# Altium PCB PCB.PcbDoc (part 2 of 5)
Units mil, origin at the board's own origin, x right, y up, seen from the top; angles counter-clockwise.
Board outline 8070.87 x 4448.94 mil, 4 copper layers (Top Layer, Layer 1, Layer 2, Bottom Layer), stack 23.756 mil thick; 263 components, 330 nets, 1677 pads, 1186 vias.
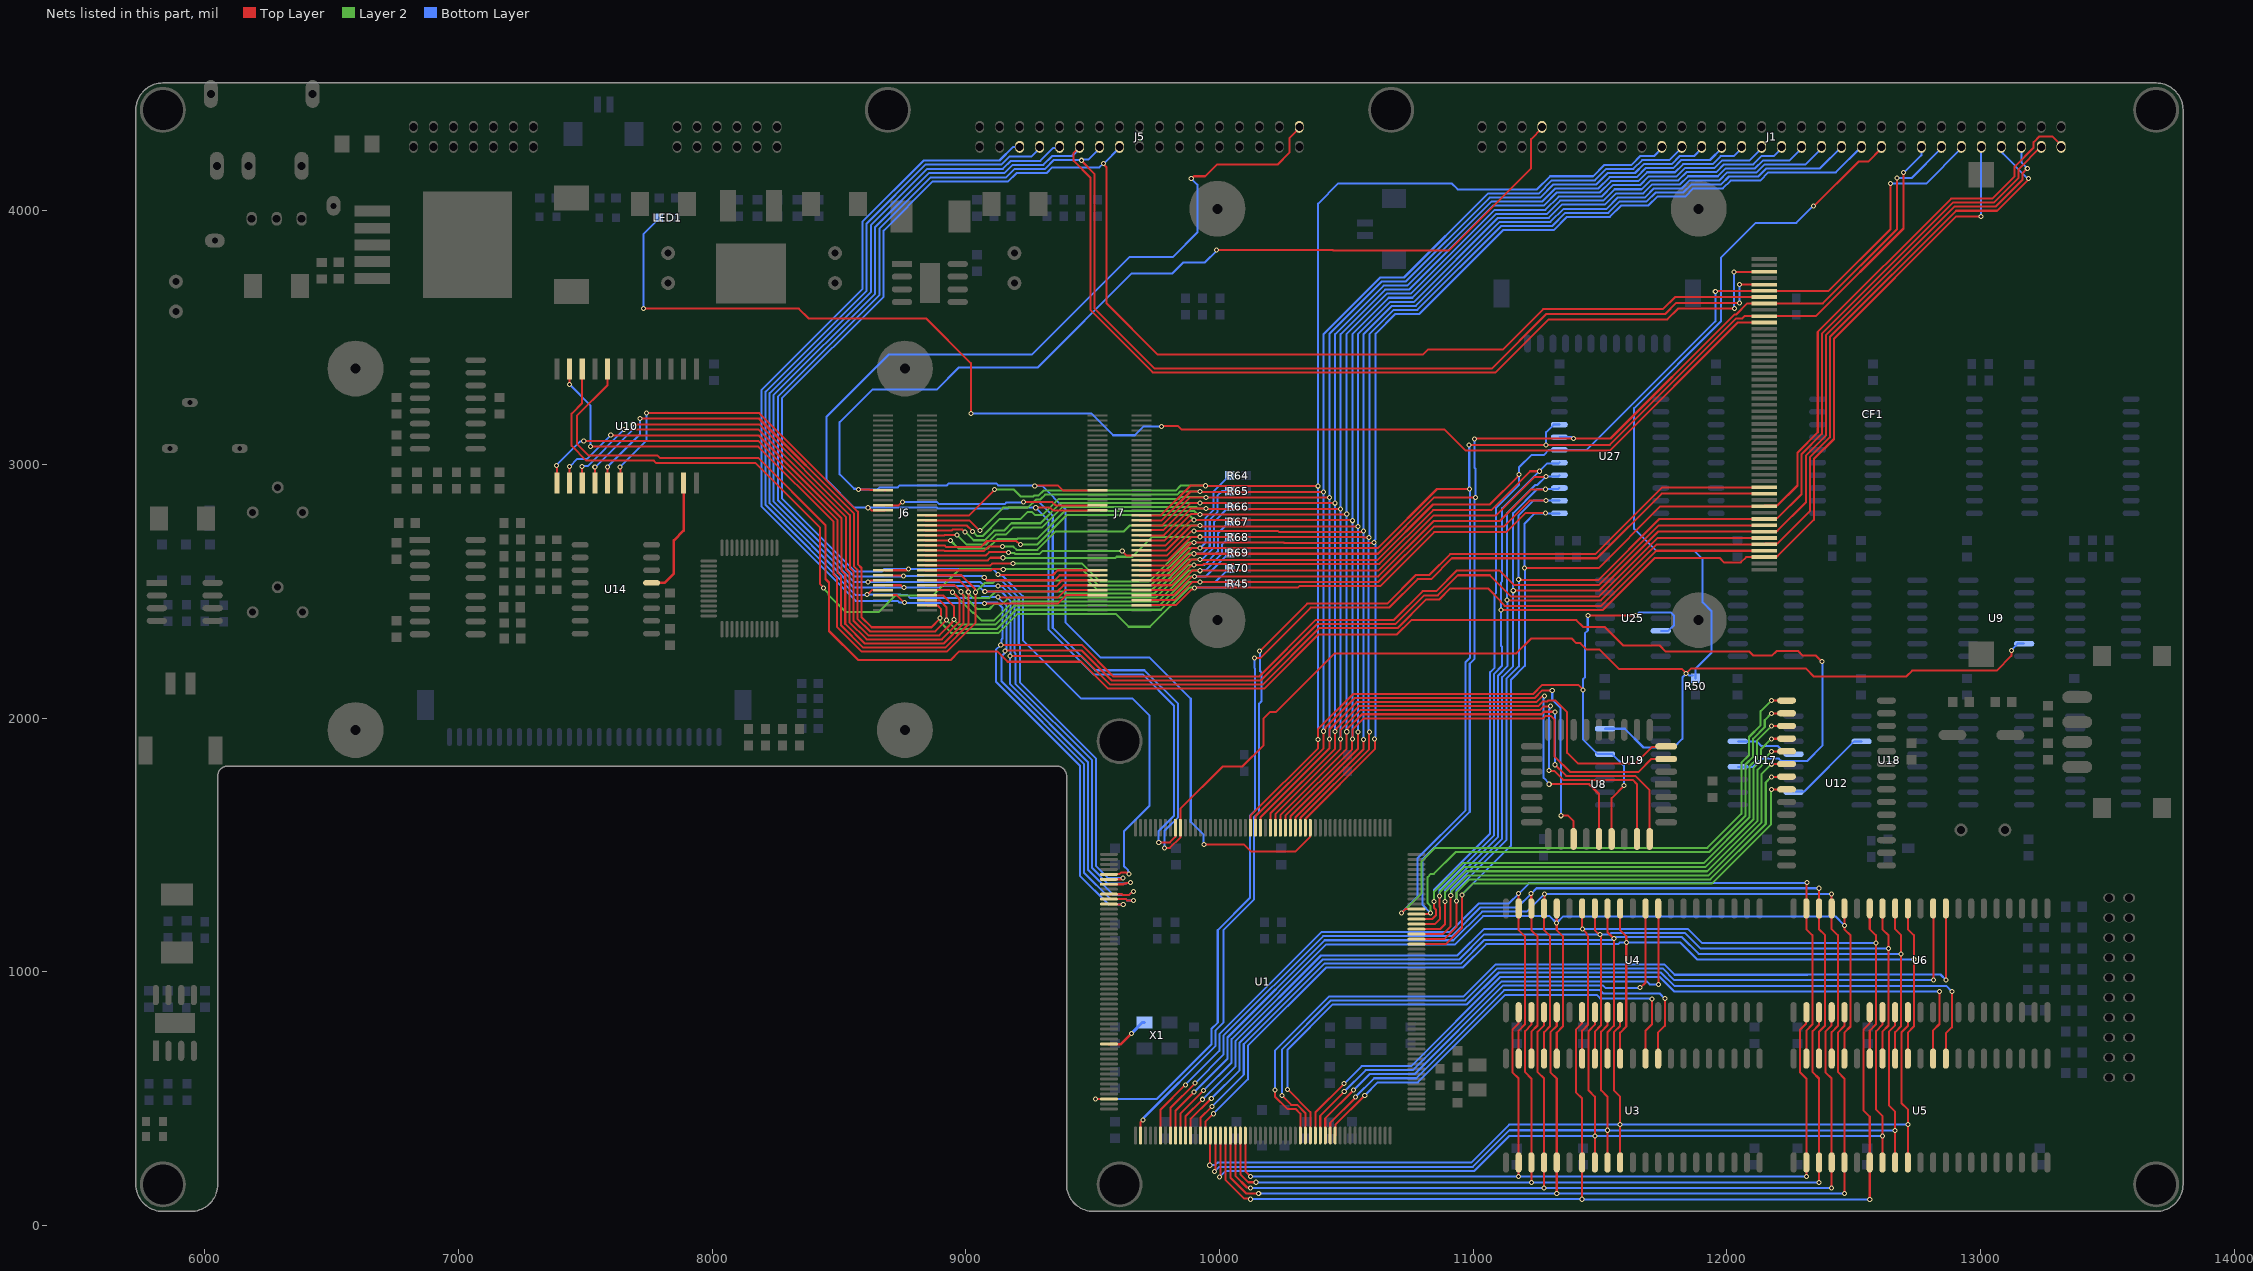
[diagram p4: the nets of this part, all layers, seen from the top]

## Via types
v1: diameter 20, hole 12, Top Layer to Bottom Layer, tented both sides, 1165 vias
v2: diameter 19.68, hole 11.81, Top Layer to Bottom Layer, tented both sides, 10 vias
v3: diameter 27.56, hole 27.56, Top Layer to Bottom Layer, 4 vias
v4: diameter 35.43, hole 35.43, Top Layer to Bottom Layer, 2 vias
v5: diameter 55.12, hole 55.12, Top Layer to Bottom Layer, 2 vias
v6: diameter 66.93, hole 66.93, Top Layer to Bottom Layer, 2 vias
v7: diameter 78.74, hole 78.74, Top Layer to Bottom Layer, 1 vias

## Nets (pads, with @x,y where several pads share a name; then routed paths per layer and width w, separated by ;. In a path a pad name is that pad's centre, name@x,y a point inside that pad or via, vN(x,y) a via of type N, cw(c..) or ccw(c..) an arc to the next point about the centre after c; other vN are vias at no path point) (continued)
A9: J1.19 J6.39 J7.39 U1.185 U8.26 U19.13 U25.5 | length 8598.6
  Top Layer w8: J6.39@8838.58,2799.21 9013.31,2799.21 9113,2898.9 v1(9113,2901) ; J7.39@9685.04,2799.21 9769.49,2799.21 9886.2,2915.92 v1(9946,2915.92) ; v1@9946.54,2916.46 9949,2914 v1(10389,2914) ; U1.185@10122.05,1567.56 10122.05,1614.3 10389,1881.25 v1(10389,1916) 10389,1957.11 10526.89,2095 11236.61,2095 11272.61,2131 11414,2131 v1(11434,2111) ; v1(11453,2404.13) v1@11640,2404.13 ; U8.26@11546.46,1523.62 11546.46,1684.56 v1(11595.89,1734)
  Layer 2 w8: v1(9113,2901) 9189,2901 9216.53,2873.47 9266.53,2873.47 9270.73,2877.66 9287.74,2877.66 9306.52,2896.44 9827.21,2896.44 9846.69,2915.92 v1(9946,2915.92)
  Bottom Layer w8: v1(10389,1916) v1(10389,2914) 10389,4027.75 10469.22,4107.97 10915.18,4107.97 10939.15,4084 11252.2,4084 11304.2,4136 11473.25,4136 11518.25,4181 11625,4181 11660,4216 11714.03,4216 11744.09,4246.06 J1.19@11744.09,4251.97 ; v1(11453,2404.13) 11452.16,2403.29 11452.16,2344.79 11441,2333.63 11441,2160.82 11434,2153.82 v1(11434,2111) 11434,1914.96 11491.16,1857.8 11549.16,1857.8 11595.94,1811.02 11595.94,1734.06 v1(11595.89,1734) ; v1(11640,2405) 11643.25,2405 11654.95,2416.7 11778.68,2416.7 11792.16,2403.23 11792.16,2366.7 11769.16,2343.7 U25.5@11740.16,2343.7
A10: J1.21 J6.37 J7.37 U1.184 U8.23 | length 7325.6
  Top Layer w8: J6.37@8838.58,2779.53 9014.43,2779.53 9054.95,2739 v1(9055.84,2739) ; J7.37@9685.04,2779.53 9772.43,2779.53 9885.94,2893.04 v1(9923.5,2893.04) 9924.54,2892 v1(10411,2892) ; U1.184@10141.73,1567.56 10142.46,1568.29 10142.46,1612.09 10411,1880.63 10411,1951.25 10418,1958.25 10418,1962.74 10534.26,2079 11243.24,2079 11273.24,2109 v1(11312.26,2109) ; v1(11347,1615) 11375,1615 11396.46,1593.54 U8.23@11396.46,1523.62
  Layer 2 w8: v1(9055.84,2739) 9056.73,2739 9147.06,2829.33 9245.02,2829.33 9277.35,2861.66 9294.37,2861.66 9313.15,2880.44 9833.83,2880.44 9846.43,2893.04 v1(9923.5,2893.04)
  Bottom Layer w8: v1(10411,1948) v1(10411,2892) 10411,3514 10634,3737 10727.73,3737 11058.57,4067.85 11258.67,4067.85 11310.67,4119.85 11479.95,4119.85 11524.95,4164.85 11631.69,4164.85 11666.69,4199.85 11773.85,4199.85 11822.83,4248.83 J1.21@11822.83,4251.97 ; v1(11312.26,2109) 11312.26,2072.74 11344.32,2040.68 11344.32,1932.94 11344,1932.62 11344,1824.89 11347,1821.89 v1(11347,1615)
A11: J1.23 J6.35 J7.35 U1.183 U8.25 | length 7522.2
  Top Layer w8: J6.35@8838.58,2759.84 9003,2759.84 v1(9026.84,2736.01) ; J7.35@9685.04,2759.84 9775.37,2759.84 9885.6,2870.07 9947.57,2870.07 v1(9947.65,2870) v1(10434,2870) ; U1.183@10161.42,1567.56 10162.15,1568.29 10162.15,1609.15 10434,1881 v1(10434,1917) 10434,1956.11 10540.89,2063 11249.87,2063 11271.57,2084.7 11280.09,2084.7 v1(11282.39,2087) ; v1(11300.31,1739.05) 11301.26,1740 11457,1740 11496.46,1700.54 U8.25@11496.46,1523.62
  Layer 2 w8: v1(9026.84,2736.01) 9045.84,2717 9065.89,2717 9134.02,2785.13 9216.02,2785.13 9242.89,2812 9262.09,2812 9274.09,2800 9302,2800 9366.44,2864.44 9840.46,2864.44 9846.76,2870.74 9946.91,2870.74 v1(9947.65,2870)
  Bottom Layer w8: v1(10434,1917) v1(10434,2870) 10434,3514.37 10640.63,3721 10734.35,3721 11065.2,4051.85 11265.3,4051.85 11317.3,4103.85 11486.57,4103.85 11531.57,4148.85 11638.32,4148.85 11673.32,4183.85 11782.85,4183.85 11815,4216 11871.51,4216 11901.57,4246.06 J1.23@11901.57,4251.97 ; v1(11282.39,2087) 11280.09,2084.7 11280.09,2078.4 11278,2076.31 11278,1764 11300.31,1741.69 v1(11300.31,1739.05)
A12: J1.25 J6.33 J7.33 U1.181 U8.4 | length 7450.4
  Top Layer w8: J6.33@8838.58,2740.16 8944.87,2740.16 8947.71,2743 8987.04,2743 8996.05,2734 v1(8997.73,2734) ; J7.33@9685.96,2741.08 9779.24,2741.08 9885.16,2847 9922.43,2847 v1(9923.5,2848.07) ; v1@9924.04,2847.54 9924.5,2848 10189.25,2848 10190.25,2847 v1(10456,2847) ; U1.181@10200.79,1567.56 10200.79,1623.79 10456,1879 10456,1950.25 10462,1956.25 10462,1959.99 10549.01,2047 11256.5,2047 11266.43,2056.93 11274.53,2065 11291.5,2065 11296.07,2069.57 11324.43,2069.57 11370.96,2023.04 11370.96,1863.04 11414,1820 11639.4,1820 11706.15,1886.75 11759.58,1886.75 U8.4@11761.46,1888.62
  Layer 2 w8: v1(8997.73,2734) 9030.73,2701 9074.37,2701 9112.21,2738.84 9150.84,2738.84 9180,2768 9294.59,2768 9375.03,2848.44 9923.13,2848.44 v1(9923.5,2848.07)
  Bottom Layer w8: v1(10456,1947) v1(10456,2847) 10456,3513.75 10647.25,3705 10740.98,3705 11071.83,4035.85 11271.93,4035.85 11323.93,4087.85 11493.2,4087.85 11538.2,4132.85 11644.95,4132.85 11679.95,4167.85 11789.47,4167.85 11821.63,4200 11934.25,4200 11980.32,4246.06 J1.25@11980.32,4251.97
A13: J1.27 J6.31 J7.31 U1.180 U8.28 | length 7709.6
  Top Layer w8: J6.31@8838.58,2720.47 8916.36,2720.47 8917.89,2722 8964.84,2722 v1(8965.84,2721) ; J7.31@9685.04,2720.47 9781.26,2720.47 9886.78,2826 v1(9946.93,2826) ; v1@9946.96,2826.04 9948,2825 v1(10478,2825) ; U1.180@10220.47,1567.56 10220.47,1620.85 10478,1878.37 v1(10478,1917) 10478,1953.37 10555.63,2031 11263.12,2031 11276.93,2044.8 11302.23,2044.8 v1(11304.53,2047.1) ; v1(11300,1794) 11302.3,1791.7 11319.41,1791.7 11355.11,1756 11630.11,1756 11646.46,1739.66 U8.28@11646.46,1523.62
  Layer 2 w8: v1(8965.84,2721) 8966.11,2721 9002.11,2685 9081,2685 9118.84,2722.84 9157.47,2722.84 9186.63,2752 9301.22,2752 9381.66,2832.44 9907.94,2832.44 9914.39,2826 v1(9946.93,2826)
  Bottom Layer w8: v1(10478,1917) v1(10478,2825) 10478,3513.12 10653.88,3689 10747.61,3689 11078.46,4019.85 11278.55,4019.85 11330.55,4071.85 11499.83,4071.85 11544.83,4116.85 11651.57,4116.85 11686.57,4151.85 11796.1,4151.85 11828.25,4184 11945,4184 11976,4215 12027.99,4215 12059.06,4246.06 J1.27@12059.06,4251.97 ; v1(11300,1794) 11300.32,1794.32 11300.32,2033.44 11302.23,2035.34 11302.23,2044.8 v1(11304.53,2047.1)
A14: J1.29 J6.29 J7.29 U1.179 U8.29 | length 7699.6
  Top Layer w8: J6.29@8838.58,2700.79 8838.98,2700.39 8939.61,2700.39 v1(8940,2700) ; J7.29@9685.04,2700.79 9784.2,2700.79 9888.41,2805 9921.5,2805 v1(9923.5,2803) ; v1@9924.5,2803 10500,2803 v1(10502,2805) ; U1.179@10240.16,1567.56 10240.16,1617.44 10502,1879.28 v1(10502,1946) 10504.3,1948.3 10504.3,1957.04 10562.26,2015 11269.75,2015 11279.68,2024.93 11321.72,2024.93 v1(11322.32,2024.32) ; v1(11323,1816) 11367,1772 11640,1772 11696.46,1715.54 U8.29@11696.46,1523.62
  Layer 2 w8: v1(8940,2700) 8971,2669 9087.63,2669 9125.47,2706.84 9203.34,2706.84 9203.5,2707 9281.37,2707 9390.82,2816.44 9901.32,2816.44 9912.46,2805.3 9921.2,2805.3 v1(9923.5,2803)
  Bottom Layer w8: v1(10502,1946) 10502,2802 10502,3514.49 10660.51,3673 10754.24,3673 11085.08,4003.85 11285.18,4003.85 11337.18,4055.85 11506.46,4055.85 11551.46,4100.85 11658.2,4100.85 11693.2,4135.85 11802.73,4135.85 11834.88,4168 11951.63,4168 11982.63,4199 12090.73,4199 12137.8,4246.06 J1.29@12137.8,4251.97 ; v1(11322.32,2024.32) 11323,2023.65 v1(11323,1816)
A15: J1.31 J6.27 J7.27 U1.178 U8.3 | length 7568.4
  Top Layer w8: J6.27@8838.58,2681.1 8916.18,2681.1 8923.29,2674 9059.89,2674 9083.89,2698 9199.75,2698 9212.75,2685 v1(9216,2685) ; J7.27@9685.04,2681.1 9788.41,2681.1 9886.57,2779.26 v1@9898.74,2779.26 ; v1(9900,2781.55) 9900.55,2781 10513.31,2781 10514.02,2780.3 10521.7,2780.3 v1(10524,2778) ; U1.178@10259.84,1567.56 10259.84,1614.49 10523,1877.65 10523,1916 v1(10524,1917) 10524,1954.11 10568.89,1999 11276.38,1999 11286.31,2008.93 11306.6,2008.93 11321.96,1993.58 11321.96,1848.16 11382.11,1788 11652.66,1788 11703.28,1838.62 U8.3@11761.46,1838.62
  Layer 2 w8: v1(9216,2685) 9217,2684 9281,2684 9397.44,2800.44 9881.11,2800.44 v1(9900,2781.55)
  Bottom Layer w8: v1(10524,1917) v1(10524,2778) 10524,3513.86 10667.14,3657 10760.86,3657 11091.71,3987.85 11291.81,3987.85 11343.81,4039.85 11513.08,4039.85 11558.08,4084.85 11664.83,4084.85 11699.83,4119.85 11809.36,4119.85 11841.51,4152 11958.25,4152 11989.25,4183 12105,4183 12137,4215 12185.47,4215 12216.54,4246.06 J1.31@12216.54,4251.97
A16: J1.33 J6.25 J7.25 U1.177 | length 6157.1
  Top Layer w8: J6.25@8838.58,2661.42 8913.24,2661.42 8916.66,2658 9071,2658 9089,2676 v1(9144.4,2676) ; J7.25@9685.04,2661.42 9791.36,2661.42 9889.2,2759.26 9923.24,2759.26 v1(9923.5,2759) ; v1@9922.15,2756 v1@9923,2755.15 ; v1@9923.15,2755.15 v1(10546,2755.15) ; U1.177@10279.53,1567.56 10280.26,1568.29 10280.26,1612.28 10546,1878.02 v1(10546,1945)
  Layer 2 w8: v1(9144.4,2676) 9188,2676 9201,2663 9282.63,2663 9355.57,2735.94 9623.94,2735.94 9647.26,2759.26 9923.24,2759.26 v1(9923.5,2759)
  Bottom Layer w8: v1(10546,1945) v1(10546,2755.15) 10546,3513.24 10673.76,3641 10767.49,3641 11098.34,3971.85 11298.44,3971.85 11350.44,4023.85 11519.71,4023.85 11564.71,4068.85 11671.46,4068.85 11706.46,4103.85 11815.98,4103.85 11848.14,4136 11964.88,4136 11995.88,4167 12111.63,4167 12143.63,4199 12248.21,4199 12295.28,4246.06 J1.33@12295.28,4251.97
A17: J1.35 J6.23 J7.23 U1.176 | length 5960.3
  Top Layer w8: J6.23@8838.58,2641.73 9079.73,2641.73 9092,2654 9168,2654 v1(9169,2653) ; v1(9617,2658) 9633.27,2641.73 9685.04,2641.73 9794.3,2641.73 9887.23,2734.67 9897.7,2734.67 v1(9900,2736.96) ; v1@9903.81,2736.96 10231.34,2736.96 10235.15,2733.15 10561.24,2733.15 10564.75,2736.67 v1(10568,2736.67) ; U1.176@10299.21,1567.56 10299.94,1568.29 10299.94,1609.34 10568,1877.4 v1(10568,1916)
  Layer 2 w8: v1(9169,2653) 9171.3,2650.7 9190.67,2650.7 9194.37,2647 9291,2647 9303,2659 9616,2659 v1(9617,2658)
  Bottom Layer w8: v1(10568,1916) 10568,2733.15 10568,3512.61 10680.39,3625 10774.12,3625 11104.97,3955.85 11305.06,3955.85 11357.06,4007.85 11526.34,4007.85 11571.34,4052.85 11678.08,4052.85 11713.08,4087.85 11822.61,4087.85 11854.76,4120 11971.51,4120 12002.51,4151 12118.25,4151 12150.25,4183 12310.95,4183 12374.02,4246.06 J1.35@12374.02,4251.97
A18: J1.37 J6.21 J7.21 U1.175 | length 6297.1
  Top Layer w8: J6.21@8838.58,2622.05 9087.05,2622.05 9097,2632 v1(9147,2632) ; J7.21@9685.04,2622.05 9797.24,2622.05 9889.86,2714.67 v1(9923.5,2714.67) 10564.24,2714.67 10566.99,2711.91 10590.16,2711.91 v1(10590.24,2712) ; U1.175@10318.9,1567.56 10319.63,1568.29 10319.63,1606.4 10590,1876.77 10590,1944 v1(10591,1945)
  Layer 2 w8: v1(9147,2632) 9148,2631 9589.5,2631 9594.5,2636 9657,2636 9735.67,2714.67 v1(9923.5,2714.67)
  Bottom Layer w8: v1(10590.24,2712) 10588.7,2710.46 10588.7,2698.97 10588,2698.27 10588,1951.25 10591,1948.25 v1(10591,1945) ; v1@10591,2711.91 10591,3512.98 10687.02,3609 10780.75,3609 11111.59,3939.85 11311.69,3939.85 11363.69,3991.85 11532.96,3991.85 11577.96,4036.85 11684.71,4036.85 11719.71,4071.85 11829.24,4071.85 11861.39,4104 11978.14,4104 12009.14,4135 12124.88,4135 12156.88,4167 12367.79,4167 J1.37@12452.76,4251.97
A19: J1.39 J6.19 J7.19 U1.174 | length 6412.7
  Top Layer w8: J6.19@8838.58,2602.36 9097.36,2602.36 9104,2609 v1(9187,2609) ; J7.19@9685.04,2602.36 9800.18,2602.36 9887.89,2690.07 9897.07,2690.07 9898.07,2691.08 9900,2689.15 9903.22,2692.37 10254.24,2692.37 10256.61,2690 10607.93,2690 v1(10610,2692.07) ; U1.174@10338.58,1567.56 10339.31,1568.29 10339.31,1603.45 10613,1877.14 10613,1916 v1(10612,1917)
  Layer 2 w8: v1(9187,2609) 9459,2609 9529,2539 9723,2539 9876.37,2692.37 v1(9900,2692.37)
  Bottom Layer w8: v1(10610,2692.07) 10610,2688.83 10616,2682.83 10616,1927.69 10614.3,1925.98 10614.3,1919.3 v1(10612,1917) ; v1@10612.3,2689.86 10612.3,2701.34 10615.7,2704.74 10615.7,3515.06 10693.65,3593 10787.37,3593 11118.22,3923.85 11318.32,3923.85 11370.32,3975.85 11539.59,3975.85 11584.59,4020.85 11691.34,4020.85 11726.34,4055.85 11835.87,4055.85 11868.02,4088 11984.76,4088 12015.76,4119 12131.51,4119 12163.51,4151 12430.53,4151 J1.39@12531.5,4251.97
A654=000#: U17.4 U17.14 | length 240.7
  Bottom Layer w8: U17.14@12043.78,1907.8 12118.2,1907.8 12136,1890 12201,1890 12233.2,1857.8 U17.4@12263.78,1857.8
A654=110#: U17.7 U18.14 | length 350.6
  Bottom Layer w8: U17.7@12263.78,1707.8 12266.46,1710.48 12305.17,1710.48 12502.5,1907.8 U18.14@12531.5,1907.8
ADLIBCS#: U10.8 U17.12 | length 6819.3
  Top Layer w8: U10.8@7588,3375.82 7588,3313 7467,3192 7467,3081 7512,3036 7784,3036 7794,3026 8181.37,3026 8447,2760.37 8447,2548.37 8461,2534.37 8461,2343.37 8575.37,2229 8941,2229 8975,2263 9124,2263 9165,2222 9455,2222 9561,2116 10177,2116 10390.7,2329.7 10700.33,2329.7 10756.63,2386 11407,2386 11434,2359 11518.88,2359 11591.88,2286 11736,2286 11760,2262 12089.75,2262 12105.75,2246 12178.37,2246 12196.37,2264 12282.38,2264 12288.38,2258 12300.38,2246 12352,2246 v1(12375,2223)
  Bottom Layer w8: U17.12@12043.78,1807.8 12103.8,1807.8 12136,1840 12206,1840 12215.2,1830.8 12316.8,1830.8 12377,1891 12377,2221 v1(12375,2223)
AEN: J1.41 J6.44 J7.44 R50.1 U1.199 U9.6 U19.15 | length 10161.4
  Top Layer w8: J6.44@8681.1,2838.58 8735.14,2838.58 8747.75,2851.2 v1(8751,2851.2) ; v1(9228,2851.33) 9341.25,2851.33 9354,2838.58 J7.44@9527.56,2838.58 ; v1(9783,1488) 9805,1488 9845.73,1528.72 9845.73,1566.83 U1.199@9846.46,1567.56 9846.46,1642.46 10013.17,1809.17 10090.54,1809.17 10173,1891.63 10173,1996.56 10200.72,2024.28 10223.65,2024.28 10454.37,2255 11170.34,2255 11229.04,2313.7 11388.79,2313.7 11407.49,2295 11423,2295 11447,2271 11498,2271 11575,2194 11822,2194 v1(11840,2176) 11859,2195 12313,2195 12344,2164 12708,2164 12731,2187 13064,2187 13122,2245 13122,2266 v1(13123,2267) ; v1(12342,4018) 12343.63,4018 12519.63,4194 12558.17,4194 12610.24,4246.06 J1.41@12610.24,4251.97
  Bottom Layer w8: v1(8751,2851.2) 8887.04,2851.2 8895.24,2843 9152.7,2843 9159.16,2849.47 9226.13,2849.47 v1(9228,2851.33) 9289.67,2851.33 9343,2798 9343,2355.39 9509.88,2188.51 9704.17,2188.51 9837,2055.68 9837,1608.86 9783,1554.86 v1(9783,1488) ; U19.15@11520.16,1957.8 11598.2,1957.8 11672,1884 11791,1884 11825,1918 11825,2159.89 11840,2174.89 v1(11840,2176) 11842.69,2176 11850.69,2168 R50.1@11867,2168 ; R50.1@11877,2157 11877,2194 11940,2257 11940,2421.37 11905,2456.37 11905,2625.37 11871.37,2659 11721.75,2659 11635,2745.75 11635,3221.37 11977,3563.37 11977,3815 12114,3952 12275,3952 v1@12344,4021 ; v1(13123,2267) 13123,2269.97 13146.73,2293.7 U9.6@13172.76,2293.7
ALE: J1.8 J6.50 J7.50 U1.173 | length 7020.7
  Top Layer w8: v1(8577,2901) 8578,2902 8619,2902 8622.73,2898.27 8680.47,2898.27 J6.50@8681.1,2897.64 ; v1(9272,2915.66) 9272.93,2916.6 9364.04,2916.6 9383,2897.64 J7.50@9527.56,2897.64 ; v1(9938.5,1501) 10097.5,1501 10125.5,1473 10298.87,1473 10357.54,1531.67 10357.54,1566.83 U1.173@10358.27,1567.56 ; v1(9989,3846) 10446.62,3846 10449.62,3843 10904,3843 11229,4168 11229,4282.15 11271.65,4324.8 J1.8@11271.65,4330.71
  Bottom Layer w8: v1(9272,2915.66) 9270.2,2917.47 9127.65,2917.47 9120.11,2925 8933.49,2925 8925.95,2917.47 8740.47,2917.47 8732.2,2909.2 8660.32,2909.2 8652.12,2901 v1(8577,2901) 8574.7,2903.3 8567.02,2903.3 8566.31,2904 8559.83,2904 8503,2960.83 8503,3166.17 8631.83,3295 8885.91,3295 8972.91,3382 9283.54,3382 9654.54,3753 9760.07,3753 9815.09,3753 9858.09,3796 9942,3796 9989,3843 v1(9989,3846) ; v1@9272.14,2915.66 9301.11,2915.66 9393,2823.78 9393,2377.08 9531.58,2238.51 9724.88,2238.51 9887,2076.39 9887,1591 9938,1540 9938,1501.5 v1(9938.5,1501)
BD0: U1.75 U3.2 U4.2 U5.2 U6.2 | length 3699.3
  Top Layer w8: U1.75@10102.36,354.33 10102.36,212.64 v1(10122,193) ; v1(11180,192) U3.2@11180,248 11180,579 11155,604 11155,772 11178.53,795.53 11178.53,838.53 U4.2@11180,840 ; v1(12314,192) U5.2@12314,248 12314,579 12289,604 12289,772 12312.53,795.53 12312.53,838.53 U6.2@12314,840
  Bottom Layer w8: v1(10122,193) 10122.5,192.5 11179.5,192.5 v1(11180,192) v1(12314,192)
BD1: U1.74 U3.3 U4.3 U5.3 U6.3 | length 3831.6
  Top Layer w8: U1.74@10082.68,354.33 10082.68,201.21 10113.89,170 v1(10144,170) ; U4.3@11230,840 11230,791 11205,766 11205,604 11230,579 U3.3@11230,248 11230.5,247.5 11230.5,169.5 v1(11231,169) ; v1(12364,169) U5.3@12364,248 12364,579 12339,604 12339,766 12364,791 U6.3@12364,840
  Bottom Layer w8: v1(10144,170) 10145,169 v1(11231,169) v1(12364,169)
BD2: U1.73 U3.4 U4.4 U5.4 U6.4 | length 3957.6
  Top Layer w8: U1.73@10062.99,354.33 10062.99,195.01 10108.7,149.3 10120.7,149.3 v1(10123,147) ; v1(11280,147) U3.4@11280,248 11280,579 11255,604 11255,764 11280,789 U4.4@11280,840 ; v1(12414,147) U5.4@12414,248 12414,579 12389,604 12389,764 12414,789 U6.4@12414,840
  Bottom Layer w8: v1(10123,147) v1(11280,147) v1(12414,147)
BD3: U1.72 U3.5 U4.5 U5.5 U6.5 | length 4084.1
  Top Layer w8: U1.72@10043.31,354.33 10043.31,188.69 10107,125 v1(10155,125) ; v1(11330,125) U3.5@11330,248 11330,579 11305,604 11305,761 11330,786 U4.5@11330,840 ; v1(12464,125) U5.5@12464,248 12464,579 12439,604 12439,761 12464,786 U6.5@12464,840
  Bottom Layer w8: v1(10155,125) v1(11330,125) v1(12464,125)
BD4: U1.71 U3.7 U4.7 U5.7 U6.7 | length 4263.2
  Top Layer w8: U1.71@10023.62,354.33 10023.62,180.38 10098.7,105.3 10120.7,105.3 v1(10123,103) ; v1(11430,103) U3.7@11430,248 11430,500 11405,525 11405,772 11428.53,795.53 11428.53,838.53 U4.7@11430,840 ; v1(12564,102) U5.7@12564,248 12564,429 12539,454 12539,772 12562.53,795.53 12562.53,838.53 U6.7@12564,840
  Bottom Layer w8: v1(10123,103) v1(11430,103) 11430.5,102.5 12563.5,102.5 v1(12564,102)
BD5: U1.70 U3.8 U4.8 U5.8 U6.8 | length 4074
  Top Layer w8: v1(10000,190) 10000,193.25 10003.94,197.18 U1.70@10003.94,354.33 ; U3.8@11480,248 v1(11480,353) 11480,507 11455,532 11455,766 11480,791 U4.8@11480,840 ; U5.8@12614,248 12614.25,248.25 12614.25,352.25 v1(12614.5,352.5) 12614.5,430.7 12589,456.2 12589,766 12614,791 U6.8@12614,840
  Bottom Layer w8: v1(10000,190) 10025,215 11005.63,215 11143.63,353 v1(11480,353) 12614,353 v1(12614.5,352.5)
BD6: U1.69 U3.9 U4.9 U5.9 U6.9 | length 4121.4
  Top Layer w8: v1(9980,212) 9980,215.25 9984.25,219.5 U1.69@9984.25,354.33 ; U3.9@11530,248 v1(11530,375) 11530,507 11505,532 11505,764 11530,789 U4.9@11530,840 ; U5.9@12664,248 v1(12664,374) 12664,448 12639,473 12639,764 12664,789 U6.9@12664,840
  Bottom Layer w8: v1(9980,212) 9999,231 10999,231 11143,375 v1(11530,375) 11530.5,374.5 12663.5,374.5 v1(12664,374)
BD7: U1.68 U3.10 U4.10 U5.10 U6.10 | length 4162.1
  Top Layer w8: v1(9962,237) 9963.84,238.84 9963.84,353.6 U1.68@9964.57,354.33 ; U3.10@11580,248 v1(11580,397) 11580,507 11555,532 11555,761 11580,786 U4.10@11580,840 ; U5.10@12714,248 v1(12714,397) 12714,457 12689,482 12689,761 12714,786 U6.10@12714,840
  Bottom Layer w8: v1(9962,237) 9963.63,238.63 9984,238.63 9992.37,247 10992.37,247 11142.37,397 v1(11580,397) v1(12714,397)
BD8: U1.67 U3.33 U4.33 U5.33 U6.33 | length 4471.3
  Top Layer w8: U1.67@9944.88,354.33 9944.88,408.88 v1(9976,440) ; U3.33@11580,657.45 11580,760 11604,784 11604,1140 11580,1164 U4.33@11580,1249.45 ; U6.33@12714,1249.45 12714,1168 12738,1144 v1(12738,1049) 12738,784 12714,760 U5.33@12714,657.45 U5.33@12715.5,655.95
  Bottom Layer w8: v1(9976,440) 10112,576 10112,707.61 10420.39,1016 10958.37,1016 11051.37,1109 11572,1109 11578,1115 v1(11605,1115) 11817,1115 11884,1048 12697.11,1048 12698.11,1049 v1(12738,1049)
BD9: U1.66 U3.34 U4.34 U5.34 U6.34 | length 4450.8
  Top Layer w8: U1.66@9925.2,354.33 9925.2,423.2 v1(9970,468) ; U4.34@11530,1249.45 11530,1156 v1(11555,1131) 11555,787 11530,762 U3.34@11530,657.45 U3.34@11530.5,656.95 ; U5.34@12664,657.45 12664,762 12688,786 v1(12688,1070) 12688,1144 12664,1168 U6.34@12664,1249.45
  Bottom Layer w8: v1(9970,468) 10096,594 10096,714.24 10413.76,1032 10951.75,1032 11044.75,1125 11545.75,1125 11551.75,1131 11558.25,1131 11564.25,1137 11822,1137 11889,1070 v1(12688,1070)
BD10: U1.64 U3.35 U4.35 U5.35 U6.35 | length 4427.5
  Top Layer w8: U1.64@9885.83,354.33 9885.83,417.83 v1(9968,500) ; U3.35@11480,657.45 11480,764 11504,788 v1@11504,1140 ; U4.35@11480,1249.45 11480,1164 v1@11498.5,1145.5 ; U6.35@12614,1249.45 12614,1168 12638,1144 v1(12638,1092) 12638,788 12614,764 U5.35@12614,657.45 U5.35@12615,656.45
  Bottom Layer w8: v1(9968,500) 10080,612 10080,720.86 10407.14,1048 10945.12,1048 11044.12,1147 v1(11500,1147) 11539.89,1147 11545.89,1153 11835,1153 11897,1091 12637,1091 v1(12638,1092)
BD11: U1.63 U3.36 U4.36 U5.36 U6.36 | length 4411.1
  Top Layer w8: U1.63@9866.14,354.33 9866.14,429.25 v1(9933.94,497.06) ; U3.36@11430,657.45 11430,768 11454,792 11454,1140 11446.88,1147.12 11446.88,1152.77 11432,1167.66 v1(11432,1169) ; v1@11430,1166 U4.36@11430,1249.45 ; U5.36@12564,657.45 12564,768 12588,792 v1(12588,1113) 12588,1144 12564,1168 U6.36@12564,1249.45
  Bottom Layer w8: v1(9933.94,497.06) 10064,627.11 10064,727.49 10400.51,1064 10938.49,1064 11043.49,1169 v1(11432,1169) 11847,1169 11903,1113 v1(12588,1113)
BD12: U1.62 U3.38 U4.38 U5.38 U6.38 | length 4340.3
  Top Layer w8: U1.62@9846.46,354.33 9846.46,440.68 v1(9936.89,531.11) ; U3.38@11330,657.45 11330,760 11354,784 11354,1140 11330,1164 U4.38@11330,1249.45 ; U5.38@12464,657.45 12464,760 12488,784 12488,1144 12464,1168 v1(12464,1183) U6.38@12464,1249.45
  Bottom Layer w8: v1(9936.89,531.11) 10048,642.23 10048,734.12 10421.88,1108 10929.14,1108 11040.14,1219 11302,1219 v1(11329,1192) 11355,1218 12429,1218 v1(12464,1183)
BD13: U1.61 U3.39 U4.39 U5.39 U6.39 | length 4427.1
  Top Layer w8: U1.61@9826.77,354.33 9826.77,452.11 v1(9899.83,525.17) ; U3.39@11280,657.45 11280,762 11304,786 11304,1140 11280,1164 U4.39@11280,1249.45 11281,1250.45 11281,1306 v1(11282,1307) ; v1(12413,1307) 12413.5,1306.5 12413.5,1249.95 U6.39@12414,1249.45 12414,1168 12438,1144 12438,786 12414,762 U5.39@12414,657.45
  Bottom Layer w8: v1(9899.83,525.17) 10032,657.34 10032,740.75 10415.25,1124 10922.51,1124 11035.51,1237 11212,1237 v1(11282,1307) v1(12413,1307)
BD14: U1.60 U3.40 U4.40 U5.40 U6.40 | length 4430.8
  Top Layer w8: U1.60@9807.09,354.33 9807.09,464.09 v1(9904,561) ; v1(11229,1308) 11229.5,1307.5 11229.5,1249.95 U4.40@11230,1249.45 11230,1164 11254,1140 11254,788 11230,764 U3.40@11230,657.45 ; U5.40@12364,657.45 12364,764 12388,788 12388,1144 12364,1168 U6.40@12364,1249.45 v1(12364,1329)
  Bottom Layer w8: v1(9904,561) 10016,673 10016,747.37 10408.63,1140 10915.88,1140 11028.88,1253 11174,1253 v1(11229,1308) 11250,1329 v1(12364,1329)
BD15: U1.58 U3.41 U4.41 U5.41 U6.41 | length 4443.9
  Top Layer w8: U1.58@9767.72,354.33 9767.72,455.83 v1(9865.94,554.06) ; U3.41@11180,657.45 11180,768 11204,792 11204,1140 11180,1164 U4.41@11180,1249.45 v1(11180,1308) ; U5.41@12314,657.45 12314,768 12338,792 12338,1144 12314,1168 U6.41@12314,1249.45 12315,1250.45 12315,1350 v1(12316,1351)
  Bottom Layer w8: v1(9865.94,554.06) 10000,688.11 10000,754 10402,1156 10909.25,1156 11022.25,1269 11141,1269 v1(11180,1308) 11221,1349 12314,1349 v1(12316,1351)
BHE#: J5.34 J6.42 J7.42 U1.200 | length 5775
  Top Layer w8: v1(8614.2,2829.2) 8617.45,2829.2 8627.75,2818.9 J6.42@8681.1,2818.9 ; v1(9276,2829.2) 9276.07,2829.27 9332.73,2829.27 9343.1,2818.9 J7.42@9527.56,2818.9 ; v1(9760.9,1510.1) 9804.48,1510.1 9826.04,1531.67 9826.04,1566.83 U1.200@9826.77,1567.56 ; v1(9889,4127) 9890.69,4127 9899.69,4136 9943.73,4136 9989.73,4182 10229,4182 10276,4229 10276,4285.84 10314.96,4324.8 J5.34@10314.96,4330.71
  Bottom Layer w8: v1@9276,2829 9276.2,2829 9327,2778.2 9327,2348.76 9503.26,2172.51 9697.54,2172.51 9821,2049.05 9821,1615.49 9760,1554.49 9760,1511 v1(9760.9,1510.1) ; v1(9276,2829.2) 9168.5,2829.2 9166.3,2827 8888.61,2827 8886.41,2829.2 8561.09,2829.2 8451,2939.29 8451,3187.71 8697.29,3434 9262,3434 9645,3817 9815.63,3817 9913,3914.37 9913,4103 v1(9889,4127)
CAS0J0: U1.93 U3.31 | length 1756.2
  Top Layer w8: U1.93@10456.69,354.33 10457.42,355.06 10457.42,396.42 v1(10573,512) ; U3.31@11680,657.45 11680,768 11706,794 v1(11706,893)
  Bottom Layer w8: v1(10573,512) 10625,564 10782.37,564 11127.37,909 11487,909 11501,895 11704,895 v1(11706,893)
CAS0J1: U1.92 U3.30 | length 1848.1
  Top Layer w8: U1.92@10437.01,354.33 10437.01,404.01 10536.44,503.44 v1(10536.44,506.56) ; U3.30@11730,657.45 11730,761 11756,787 v1(11756,894)
  Bottom Layer w8: v1(10536.44,506.56) 10609.89,580 10775.75,580 11122.75,927 11500.37,927 11512.37,915 11735,915 v1(11756,894)
CAS1J0: U1.91 U4.31 | length 1852.5
  Top Layer w8: U1.91@10417.32,354.33 10417.32,421.65 v1(10529.31,533.63) ; v1(11659,937) 11660,937 11680,957 U4.31@11680,1249.45
  Bottom Layer w8: v1(10529.31,533.63) 10591.67,596 10769.12,596 11119.12,946 11512,946 11522,936 11658,936 v1(11659,937)
CAS1J1: U1.90 U4.30 | length 1936
  Top Layer w8: U1.90@10397.64,354.33 10397.64,431.64 10492.28,526.28 v1(10492.28,527.72) ; U4.30@11730,1249.45 11730.5,1248.95 11730.5,950.5 v1(11731,950)
  Bottom Layer w8: v1(10492.28,527.72) 10576.56,612 10762.49,612 11112.49,962 11683.88,962 11695.88,950 v1(11731,950)
CAS2J0: U1.89 U5.31 | length 3071.4
  Top Layer w8: U1.89@10377.95,354.33 10377.95,444.95 v1(10492,559) ; U5.31@12814,657.45 12814,769 12839,794 v1(12839,922)
  Bottom Layer w8: v1(10492,559) 10561,628 10755.86,628 11106.86,979 11736.12,979 11793.12,922 v1(12839,922)
CAS2J1: U1.88 U5.30 | length 3426.3
  Top Layer w8: v1(10269,536) 10358.27,446.73 U1.88@10358.27,354.33 ; U5.30@12864,657.45 12864,757 12888,781 v1(12888,922)
  Bottom Layer w8: v1(10269,536) 10269,693.37 10446.63,871 10976.24,871 11102.24,997 11740.75,997 11793.75,944 12866,944 v1(12888,922)
CAS3J0: U1.87 U6.31 | length 3393.5
  Top Layer w8: v1(10247,512) 10247,511 10283,475 10306.63,475 10338.58,443.04 U1.87@10338.58,354.33 ; U6.31@12814,1249.45 12814.5,1248.95 12814.5,967.5 v1(12815,967)
  Bottom Layer w8: v1(10247,512) 10247,694 10440,887 10969.61,887 11095.61,1013 11747.37,1013 11793.37,967 v1(12815,967)
CAS3J1: U1.86 U6.30 | length 3490.8
  Top Layer w8: v1(10219,534) 10219,507.89 10267.89,459 10300,459 10318.9,440.1 U1.86@10318.9,354.33 ; U6.30@12864,1249.45 12864.5,1248.95 12864.5,967.5 v1(12865,967)
  Bottom Layer w8: v1(10219,534) 10219,688.63 10433.37,903 10962.98,903 11088.98,1029 11754,1029 11795,988 12318.5,988 12319.5,989 12843,989 v1(12865,967)
CFCS0#: CF1.7 U1.50 | length 4473.8
  Top Layer w8: v1(9511,499) 9511.33,498.67 9564.32,498.67 U1.50@9564.65,498.35 ; v1(10138,2236) 10161,2236 10360,2435 10668.51,2435 10781.51,2548 10834.75,2548 10916.75,2630 11488.73,2630 11743.37,2884.65 CF1.7@12147.64,2884.65
  Bottom Layer w8: v1(9511,499) 9754,499 9968,713 9968,774 9993.45,799.45 9993.45,1164.08 10120,1290.63 10120,1614.63 10141,1635.63 10141,2195.03 10138,2198.03 v1(10138,2236)
CFCS1#: CF1.32 U1.54 | length 4367.7
  Top Layer w8: U1.54@9688.98,354.33 9688.98,405.98 v1(9698,415) ; v1(10157.44,2263.56) 10158.92,2263.56 10346.37,2451 10661.88,2451 10774.88,2564 10828.12,2564 10910.12,2646 11482.1,2646 11745.74,2909.65 CF1.32@12147.64,2909.65
  Bottom Layer w8: v1(9698,415) 9698,418.25 9702.87,423.12 9702.87,425.24 9984,706.37 9984,767.37 10017,800.37 10017,1165 10136,1284 10136,1608 10157,1629 10157,2056.96 10165.44,2065.39 10165.44,2180.11 10160,2185.55 10160,2245.11 10159.74,2245.37 10159.74,2261.26 v1(10157.44,2263.56)
CFLED#: CF1.45 LED1.2 | length 5390.3
  Top Layer w8: v1(7729,3615) 7729.56,3614.44 8341.59,3614.44 8380.73,3575.31 8843.96,3575.31 9020,3399.27 v1(9020,3200) ; v1(9771,3150) 9772,3151 9837,3151 9850,3138 10887,3138 10971,3054 11539,3054 12044.65,3559.65 CF1.45@12147.64,3559.65
  Bottom Layer w8: v1(7729,3615) 7729,3908.13 7791.34,3970.47 LED1.2@7791.34,3972.44 ; v1(9020,3200) 9496,3200 9581,3115 9667,3115 9702,3150 v1(9771,3150)
CLK: U10.23 U14.5 | length 476.1
  Top Layer w10: U14.5@7761.34,2533 7812,2533 7849,2570 7849,2700 7888,2739 U10.23@7888,2927
CLK2: U1.39 X1.3 | length 175.1
  Top Layer w10: U1.39@9564.65,714.88 9611.88,714.88 v1(9654,757)
  Bottom Layer w12: v1(9654,757) 9654,757.87 9696.13,800 X1.3@9704,800
D0: CF1.21 J1.45 J6.17 J7.17 R64.1 U1.145 U10.10 U12.15 U27.18 | length 12135.5
  Top Layer w8: U10.10@7488,3375.82 7488,3242 7446,3200 7446,3073 7504,3015 7770,3015 7780,3005 8172,3005 8425,2752 8425,2529.88 8439,2515.88 v1(8439,2512.77) ; J6.17@8838.58,2582.68 9100.3,2582.68 9104.96,2587.33 9146.62,2587.33 v1(9147.87,2586.09) ; J7.17@9685.04,2582.68 9803.12,2582.68 9890.52,2670.07 v1(9923.5,2670.07) 10625.03,2670.07 10857.96,2903 v1(10986,2903) ; v1(10718,1231) 10718,1231.89 10732.49,1246.38 U1.145@10776.77,1246.38 ; v1(10984,3077) 11539.37,3077 12038.02,3575.65 12061.27,3575.65 12070.27,3584.65 CF1.21@12147.64,3584.65 12351.65,3584.65 12697,3930 v1(12697,4151) ; v1(12176,2069) 12176.05,2068.95 U12.15@12236.22,2068.9 U12.15@12236.22,2068.9 U12.15@12235.77,2068.45
  Layer 2 w8: v1(8439,2512.77) 8439,2511.66 8458.38,2492.27 8458.38,2486.62 8527,2418 8657,2418 8723,2484 8872,2484 8975.33,2587.33 9146.62,2587.33 v1(9147.87,2586.09) 9148.78,2587 9458.37,2587 9522.37,2523 9729.63,2523 9876.7,2670.07 v1(9923.5,2670.07) ; v1(10718,1231) 10797,1310 10797,1435 10850,1488 11924,1488 12058,1622 12058,1823.51 12088,1853.51 12088,1925.25 12134,1971.25 12134,2027 v1(12176,2069)
  Bottom Layer w8: v1(9923.5,2670.07) 9945.5,2692.07 9945.5,2789.5 9976,2820 9976,2892.5 10039.5,2956 R64.1@10041,2956 ; v1(10718,1231) 10718,1231.89 10781,1294.89 10781,1447.15 10971,1637.15 10971,2220.9 10988,2237.9 10988,2901 10985,2904 10985,3076 v1(10984,3077) ; v1(11288,3077) 11288,3127.4 11317.69,3157.09 U27.18@11340.16,3157.09 ; v1(12697,4151) 12700,4151 12767.72,4218.72 J1.45@12767.72,4251.97
D1: CF1.22 J1.47 J6.15 J7.15 R65.1 U1.144 U10.11 U12.16 U27.17 | length 12108.9
  Top Layer w8: v1(7438,3315) U10.11@7438,3375.82 ; v1(7520,3070) 8182.63,3070 8479,2773.63 8479,2565.91 8493,2551.91 8493,2358.24 8589.24,2262 8925.75,2262 9037.99,2374.24 v1(9037.99,2495.97) 9036.46,2497.5 9036.46,2509.54 8983.01,2562.99 J6.15@8838.58,2562.99 ; J7.15@9685.04,2562.99 9806.07,2562.99 9888.56,2645.48 9899.48,2645.48 9901.78,2647.78 10625.36,2647.78 10847.59,2870 v1(11010,2870) ; U1.144@10776.77,1226.69 10823.45,1226.69 10828.75,1232 v1(10832,1232) ; v1(11006,3101) 11006.5,3101.5 11395.5,3101.5 v1(11396,3102) 11541.75,3102 12031.39,3591.65 12038.76,3591.65 12081.76,3634.65 CF1.22@12147.64,3634.65 12378.65,3634.65 12672,3928 12672,4128 v1(12671,4129) ; v1(12176,2018) 12176.45,2018.45 U12.16@12235.77,2018.45
  Layer 2 w8: v1(9037.99,2495.97) 9074.03,2532 9106.58,2532 9117.78,2543.2 9479.55,2543.2 9515.75,2507 9736.25,2507 9877.03,2647.78 v1(9900,2647.78) ; v1(10832,1232) 10832,1259.89 10821,1270.89 10821,1373.11 10833.89,1386 10845.89,1386 10931.89,1472 11930.63,1472 12074,1615.37 12074,1816.88 12104,1846.88 12104,1918.63 12150,1964.63 12150,1992 v1(12176,2018)
  Bottom Layer w8: v1(7438,3315) 7520,3233 v1(7520,3070) ; v1(9900,2647.78) 9932.32,2647.78 9962,2677.46 9962,2781.5 9992,2811.5 9992,2876 10011,2895 R65.1@10041,2895 ; v1(10832,1232) 10801,1263 10801,1444.52 10987,1630.52 10987,2214.27 11005,2232.27 11005,2861.75 11010,2866.75 v1(11010,2870) ; v1@11006,2871 11010,2875 11010,2982.5 11006,2986.5 v1(11006,3101) ; U27.17@11340.16,3107.09 11387.66,3107.09 11392.75,3102 v1(11396,3102) ; v1(12671,4129) 12729.39,4129 12846.46,4246.06 J1.47@12846.46,4251.97
D2: CF1.23 J1.49 J6.13 J7.13 R66.1 U1.143 U10.13 U12.17 U27.16 | length 11889.6
  Top Layer w8: U10.13@7388,2927 v1@7388,2996 ; v1(7494,3093) 8182.25,3093 8495,2780.25 8495,2572.54 8509,2558.54 8509,2364.86 8595.86,2278 8919.12,2278 9010,2368.88 v1@9010,2496.56 ; J6.13@8838.58,2543.31 8974.69,2543.31 9007.92,2510.09 v1@9007.92,2498.64 ; J7.13@9685.04,2543.31 9809.01,2543.31 9890.89,2625.18 v1(9923.07,2625.18) ; v1@9924.5,2624 10624.21,2624 10842.21,2842 11066,2842 11175.44,2951.44 11175.44,2952.2 11181,2957.75 v1(11181,2961) ; U1.143@10776.77,1207.01 10838.12,1207.01 10854,1222.89 10854,1244.32 10846,1252.32 v1(10846,1277) ; v1(11955,3681.65) 11956.5,3683.15 12146.14,3683.15 CF1.23@12147.64,3684.65 ; CF1.23@12147.64,3684 12402,3684 12646,3928 v1(12646,4107) ; v1(12176,1968) 12176.45,1968.45 U12.17@12235.77,1968.45
  Layer 2 w8: v1(9010,2497.06) 9010,2493.81 9015.99,2487.82 9015.99,2486.85 9028.88,2473.97 9092.81,2473.97 9117.84,2499 9381.52,2499 9389.52,2491 9742.88,2491 9877.36,2625.48 9922.78,2625.48 v1(9923.07,2625.18) ; v1(10846,1277) 10846,1314.62 10959.38,1428 11909.25,1428 12090,1608.75 12090,1810.25 12120,1840.25 12120,1912 v1(12176,1968)
  Bottom Layer w8: v1(7386,2996) 7480.7,3090.7 7491.7,3090.7 v1(7494,3093) ; v1(9923.07,2625.18) 9925.37,2627.48 9934.65,2627.48 9978,2670.83 9978,2772.5 10039.5,2834 R66.1@10041,2834 ; v1(10846,1277) 10846,1323.89 11067,1544.89 11067,2181.14 11085,2199.14 11085,2488.44 11090.83,2494.27 11090.83,2829.2 11181.44,2919.82 11181.44,2960.56 v1(11181,2961) 11181,2988 11231,3038 11280.11,3038 11299.21,3057.09 U27.16@11340.16,3057.09 11448.09,3057.09 11955,3564 v1(11955,3681.65) ; v1(12646,4107) 12786.13,4107 12925.2,4246.06 J1.49@12925.2,4251.97
D3: CF1.2 J1.51 J6.11 J7.11 R67.1 U1.142 U10.14 U12.18 U27.15 | length 12697.4
  Top Layer w8: U10.14@7438,2927 v1(7438,2991) ; v1(7600.39,3115.61) 7602,3114 8183.88,3114 8511,2786.88 8511,2579.17 8525,2565.17 8525,2371.49 8602.49,2294 8912.5,2294 8990.93,2372.44 8990.93,2484.33 8982,2493.26 8982,2498.11 8956.49,2523.62 J6.11@8838.58,2523.62 ; J7.11@9685.04,2523.62 9811.95,2523.62 9889.22,2600.89 9899.89,2600.89 v1@9901,2602 ; v1(9900,2603.18) 9933.8,2603.18 9938.61,2608 10630.84,2608 10842.84,2820 11072.11,2820 11225.11,2973 v1(11262,2973) ; U1.142@10776.77,1187.32 10849.32,1187.32 10870,1208 10870,1253.86 10868,1255.86 v1(10868,1299) ; v1(11110,2426.13) 11511.13,2426.13 11716,2631 11972,2631 11989,2614 12056,2614 12076.65,2634.65 CF1.2@12147.64,2634.65 12150.89,2637.9 12200.11,2637.9 12344,2781.79 12344,3021.25 12423,3100.25 12423,3495.82 12905.18,3978 v1(13003,3978) ; v1(12176,1918) 12176.45,1918.45 U12.18@12235.77,1918.45
  Layer 2 w8: v1(8982,2498) 8982,2494.87 8988,2488.87 8988,2487.44 9045.48,2429.97 9093.74,2429.97 9112.77,2449 9144,2449 9170,2475 9749.51,2475 9877.69,2603.18 v1(9900,2603.18) ; v1(10868,1299) 10870.3,1301.3 10870.3,1316.29 10966.01,1412 11915.88,1412 12106,1602.12 12106,1803.63 12136,1833.63 12136,1878 v1(12176,1918)
  Bottom Layer w8: v1(7438,2991) 7469,3022 7507,3022 7600.39,3115.39 v1(7600.39,3115.61) ; v1(9900,2603.18) 9940.18,2603.18 9994,2657 9994,2727.5 10039.5,2773 R67.1@10041,2773 ; v1(10868,1299) 10868,1323.26 11083,1538.26 11083,2174.51 11113.65,2205.16 11113.65,2281.13 11110,2284.78 v1(11110,2426.13) 11109.69,2426.44 11109.69,2533.77 11115,2539.08 11115,2827.34 11290.76,3003.09 11336.16,3003.09 U27.15@11340.16,3007.09 ; v1(13003,3978) 13003,4251.03 J1.51@13003.94,4251.97
D4: CF1.3 J1.53 J6.9 J7.9 R68.1 U1.141 U10.15 U12.19 U27.14 | length 12672.3
  Top Layer w8: v1(7487,2991) 7487.5,2990.5 7487.5,2927.5 U10.15@7488,2927 ; v1(7652,3137) 8183.51,3137 8527,2793.51 8527,2585.79 8541,2571.79 8541,2378.12 8609.12,2310 8905.87,2310 8974.93,2379.06 8974.93,2471.31 8950.25,2496 v1(8947,2496) 8944.25,2496 8936.31,2503.94 J6.9@8838.58,2503.94 ; J7.9@9685.04,2503.94 9816,2503.94 9892.95,2580.89 v1(9923.5,2580.89) 10626.36,2580.89 10844.47,2799 11091,2799 11243,2951 11286,2951 v1(11287,2952) ; U1.141@10776.77,1167.64 10869.64,1167.64 10890,1188 v1(10890,1277) ; v1(11133.65,2464.65) 11134.29,2464 11503.75,2464 11724.39,2684.65 CF1.3@12147.64,2684.65 12150.89,2687.9 12200.11,2687.9 12328,2815.79 12328,3027.88 12407,3106.88 12407,3502.45 12904.55,4000 13066.25,4000 13190,4123.75 v1(13190,4127) ; v1(12176,1868) 12176.45,1868.45 U12.19@12235.77,1868.45
  Layer 2 w8: v1(8947,2496) 9027.85,2415.15 9031.74,2415.15 9062.89,2384 9110,2384 9185,2459 9756.14,2459 9878.03,2580.89 v1(9923.5,2580.89) ; v1(10890,1277) 10890,1313.37 10972.63,1396 11922.51,1396 12122,1595.49 12122,1797 12152,1827 12152,1844 v1(12176,1868)
  Bottom Layer w8: v1(7487,2991) 7489.25,2993.25 7509.13,2993.25 7652,3136.11 v1(7652,3137) ; v1(9923.5,2580.89) 9925.8,2583.18 9946.18,2583.18 10010,2647 10010,2682.5 10039.5,2712 R68.1@10041,2712 ; v1(10890,1277) 10890,1322.63 11099,1531.63 11099,2167.88 11135.65,2204.53 11135.65,2462.64 v1(11133.65,2464.65) ; v1@11135,2466 11133.65,2467.35 11133.65,2806.39 11246.35,2919.09 11254.09,2919.09 v1(11287,2952) 11287,2953.09 11336.16,2953.09 U27.14@11340.16,2957.09 ; J1.53@13082.68,4251.97 13087.93,4246.72 13087.93,4226.07 13187,4127 v1(13190,4127)
D5: CF1.4 J1.55 J6.7 J7.7 R69.1 U1.140 U10.16 U12.20 U27.13 | length 12271
  Top Layer w8: U10.16@7538,2927 v1@7538,2990 ; v1(7687,3160) 7689,3158 8185.14,3158 8543,2800.14 8543,2592.42 8557,2578.42 8557,2384.75 8615.75,2326 8896.11,2326 8946.76,2376.65 8946.76,2378.76 8952.93,2384.93 8952.93,2441.07 8910.67,2483.33 J6.7@8839.5,2483.33 ; J7.7@9685.04,2484.25 9818.94,2484.25 9890.99,2556.3 9899.47,2556.3 v1(9901.77,2558.59) ; v1@9900.59,2558.59 10626.69,2558.59 10845.1,2777 11105,2777 11230,2902 v1(11286,2902) ; U1.140@10776.77,1147.95 10881.07,1147.95 10912,1178.89 v1(10912,1300) ; v1(11158.52,2502) 11496.49,2502 11729.14,2734.65 CF1.4@12147.64,2734.65 12150.89,2737.9 12200.11,2737.9 12312,2849.79 12312,3034.51 12391,3113.51 12391,3509.08 12897.92,4016 13059.62,4016 13167,4123.38 13167,4149 v1(13185,4167) ; v1(12176,1818) 12176.45,1818.45 U12.20@12235.77,1818.45
  Layer 2 w8: v1(8952.93,2388.18) 8973.11,2368 9116.63,2368 9191.63,2443 9762.76,2443 9878.36,2558.59 v1(9901.77,2558.59) ; v1(10912,1300) 10914.3,1302.3 10914.3,1315.04 10979.26,1380 11929.14,1380 12138,1588.86 12138,1780 v1(12176,1818)
  Bottom Layer w8: v1(7537.5,2990.5) 7540.61,2990.5 7687,3136.89 v1(7687,3160) ; v1(9901.77,2558.59) 9947.09,2558.59 10039.5,2651 R69.1@10041,2651 ; v1(10912,1300) 10912.88,1300.88 10912.88,1322.89 11115,1525.01 11115,2161.25 11158,2204.25 11158,2501.48 v1(11158.52,2502) ; v1@11159,2502 11158.08,2502.92 11158.08,2808.19 11252.98,2903.09 11336.16,2903.09 U27.13@11340.16,2907.09 ; J1.55@13161.42,4251.97 13161.42,4190.58 v1(13185,4167)
D6: CF1.5 J1.57 J6.5 J7.5 R70.1 U1.139 U10.17 U12.21 U27.12 | length 12076.6
  Top Layer w8: U10.17@7588,2927 v1@7588,2990 ; v1(7715,3181) 8184.76,3181 8559,2806.76 8559,2599.05 8573,2585.05 8573,2391.37 8622.37,2342 8880,2342 8923.77,2385.77 v1(8924.76,2385.77) ; J6.5@8839.5,2463.65 8897.35,2463.65 8924,2437 v1@8924,2386 ; J7.5@9685.04,2464.57 9821.88,2464.57 9893.32,2536 9923.5,2536 9923.8,2536.3 10627.02,2536.3 10845.72,2755 11121,2755 11223,2857 v1(11287,2857) ; U1.139@10776.77,1128.27 10886.27,1128.27 10934,1176 v1(10934,1278) ; v1(11180.08,2546) 11182.08,2544 11493.24,2544 11733.88,2784.65 CF1.5@12147.64,2784.65 12150.89,2787.9 12200.11,2787.9 12295,2882.79 12295,3040.14 12375,3120.14 12375,3515.7 12891.3,4032 13052.99,4032 13151,4130.01 13151,4164.11 13238.86,4251.97 J1.57@13240.16,4251.97 ; v1(12176,1768) 12176.45,1768.45 U12.21@12235.77,1768.45
  Layer 2 w8: v1(8924.76,2385.77) 8924.76,2385.24 8958,2352 9123.25,2352 9198.25,2427 9769.39,2427 9878.69,2536.3 v1(9923.5,2536.3) ; v1(10934,1278) 10934,1312.11 10985.89,1364 11935.76,1364 12154,1582.24 12154,1746 v1(12176,1768)
  Bottom Layer w8: v1(7587.5,2990.5) 7715,3118 v1(7715,3181) ; v1(9923.5,2536.3) 9984.3,2536.3 10024.5,2576.5 10027.5,2576.5 R70.1@10041,2590 ; v1(10934,1278) 10934,1321.38 11131,1518.38 11131,2154.63 11180.52,2204.15 11180.52,2543.64 11180.08,2544.08 11180.08,2799.08 11238.09,2857.09 U27.12@11340.16,2857.09
D7: CF1.6 J1.59 J6.3 J7.3 R45.1 U1.138 U10.18 U12.22 U27.11 | length 11999.5
  Top Layer w8: U10.18@7638,2927 v1@7638,2990 ; v1@7741,3202 8186.39,3202 8575,2813.39 8575,2605.68 8589,2591.68 8589,2398 8629,2358 8864.89,2358 8898,2391.11 8898,2397.25 8902,2401.25 8902,2430.72 8888.56,2444.16 8847.18,2444.16 J6.3@8846.46,2444.88 ; J7.3@9685.04,2444.88 9828.31,2444.88 9891.16,2507.73 9892.91,2507.73 9897.97,2512.79 v1(9901.21,2512.79) 9902.43,2514 10308.89,2514 10315.19,2520.3 10633.65,2520.3 10846.35,2733 11130.88,2733 11205.88,2808 v1(11286,2808) ; U1.138@10776.77,1108.58 10892.58,1108.58 10956,1172 v1(10956,1303) ; v1(11203,2591) 11494.98,2591 11738.63,2834.65 CF1.6@12147.64,2834.65 12150.89,2837.9 12200.11,2837.9 12279,2916.79 12279,3046.76 12359,3126.76 12359,3522.33 12884.67,4048 13046.36,4048 13135,4136.64 13135,4174 13210.44,4249.44 13210.44,4270.18 13233.26,4293 13283.77,4293 13318.9,4257.87 J1.59@13318.9,4251.97 ; v1(12176,1718) 12176.45,1718.45 U12.22@12235.77,1718.45
  Layer 2 w8: v1(8898,2394) 8900.3,2391.7 8900.3,2378.59 8942.89,2336 9129.88,2336 9204.88,2411 9591,2411 9642,2360 9726,2360 9880,2514 9900,2514 v1(9901.21,2512.79) ; v1(10956,1303) 11001,1348 11942.39,1348 12174,1579.61 12174,1716 v1(12176,1718)
  Bottom Layer w8: v1(7637.5,2990.5) 7742,3095 7742,3202 v1(7741,3203) ; v1(9901.21,2512.79) 9902.43,2514 10021.31,2514 10022.81,2515.5 10027.5,2515.5 R45.1@10041,2529 ; v1(10956,1303) 11149,1496 11149,2150 11204.44,2205.44 11204.44,2589.56 v1(11203,2591) 11202.79,2591.21 11202.79,2766.79 11243.09,2807.09 U27.11@11340.16,2807.09
D8: CF1.47 J5.15 J6.18 J7.18 U1.5 | length 8796
  Top Layer w8: J6.18@8681.1,2582.68 8766.43,2582.68 8771.75,2588 v1(8775,2588) ; v1(9126.89,2565.33) 9128.13,2564.09 9344.09,2564.09 9362.68,2582.68 J7.18@9527.56,2582.68 ; v1(9543.06,4186.06) 9543.06,4182.81 9555,4170.87 9555,3635.51 9757.51,3433 10802.51,3433 10821.97,3452.46 11116.46,3452.46 11276,3612 11748.62,3612 11796.27,3659.65 CF1.47@12147.64,3659.65 ; U1.5@9564.65,1384.17 9565.37,1384.9 9605.62,1384.9 9611.47,1390.75 9634.89,1390.75 9639.7,1385.94 v1(9642.94,1385.94)
  Bottom Layer w8: v1(8775,2588) 8678.88,2588 8667.88,2577 8564.39,2577 8275,2866.39 8275,3260.61 8676,3661.61 8676,3922 8868.71,4114.71 9165.99,4114.71 9200.27,4149 9319.25,4149 9341.25,4171 9526.89,4171 9541.94,4186.06 v1(9543.06,4186.06) ; v1@8776,2588 9107,2588 9126.89,2568.11 v1(9126.89,2565.33) 9129.18,2563.04 9142.96,2563.04 9225,2481 9225,2307 9455.49,2076.51 9657.78,2076.51 9725,2009.29 9725,1655.25 9624,1554.25 9624,1415.26 9640,1399.26 9640,1396.63 9640.65,1395.98 9640.65,1388.24 v1(9642.94,1385.94) ; v1@9541.89,4186 9544.62,4186 9606.3,4247.68 J5.15@9606.3,4251.97
D9: CF1.48 J5.13 J6.16 J7.16 U1.6 | length 8776.7
  Top Layer w8: J6.16@8681.1,2562.99 8682.02,2562.07 8753.61,2562.07 v1(8755,2560.68) ; v1(9073,2554) 9083.73,2543.27 9350.27,2543.27 9369.99,2562.99 J7.16@9527.56,2562.99 ; v1(9456.54,4199) 9456.54,4196.21 9507,4145.75 9507,3615.63 9743.63,3379 11075,3379 11289.06,3593.06 11757.06,3593.06 11801,3637 v1(12050,3637) ; U1.6@9564.65,1364.49 9613.07,1364.49 9617.33,1368.75 v1(9620.58,1368.75) ; v1(12050,3709) 12050.18,3708.82 12148.46,3708.82 CF1.48@12148.64,3708.65
  Bottom Layer w8: v1(8755,2560.68) 8752.7,2558.38 8744.69,2558.38 8744.31,2558 8560.76,2558 8259,2859.76 8259,3267.24 8659.29,3667.52 8659.29,3928.92 8861.79,4131.43 9159.07,4131.43 9192.64,4165 9312.63,4165 9347.63,4200 9455.54,4200 v1(9456.54,4199) ; v1@8758.68,2560.68 9063.08,2560.68 v1@9069.75,2554 ; v1(9073,2554) 9083.73,2543.27 9140.11,2543.27 9209,2474.37 9209,2293 9213,2289 9213,2140.63 9514,1839.63 9514,1416 9561.25,1368.75 v1(9620.58,1368.75) ; v1@9460,4200 9461,4199 9463.3,4201.3 9482.79,4201.3 9527.56,4246.06 J5.13@9527.56,4251.97 ; v1(12050,3637) v1(12050,3709)
D10: CF1.49 J5.11 J6.14 J7.14 U1.7 | length 8920.7
  Top Layer w8: v1(8615,2536) 8618.25,2536 8624.83,2542.58 8680.38,2542.58 J6.14@8681.1,2543.31 ; v1(9126.89,2521.2) 9127.76,2520.33 9356.33,2520.33 9379.31,2543.31 J7.14@9527.56,2543.31 ; J5.11@9448.82,4251.97 9425,4228.15 9425,4197 9491,4131 9491,3609 9737,3363 11088.78,3363 11297.78,3572 11766,3572 11808,3614 v1(12030,3614) ; U1.7@9564.65,1344.8 9621.69,1344.8 9623.89,1347 9629.94,1347 9632.65,1349.7 9647.7,1349.7 v1(9650,1352) ; v1(12029,3759) 12029.32,3759.32 12148.32,3759.32 CF1.49@12148.64,3759.65
  Bottom Layer w8: v1(8615,2536) 8560.14,2536 8243,2853.14 8243,3273.86 8642.57,3673.43 8642.57,3935.85 8854.87,4148.14 9152.14,4148.14 9185,4181 9306,4181 9341,4216 9418.76,4216 9448.82,4246.06 J5.11@9448.82,4251.97 ; v1@8617,2536 9058,2536 9072.8,2521.2 v1(9126.89,2521.2) 9129.18,2518.9 9141.84,2518.9 9193,2467.75 9193,2258.11 9197,2254.11 9197,2134 9498,1833 9498,1409 9560.25,1346.75 9623.64,1346.75 9623.89,1347 9629.94,1347 9632.65,1349.7 9647.7,1349.7 v1(9650,1352) ; v1(12029,3759) 12028,3758 12028,3616 v1(12030,3614)
D11: CF1.27 J5.9 J6.12 J7.12 U1.9 | length 8603.7
  Top Layer w8: J6.12@8681.1,2523.62 8744.13,2523.62 8753.75,2514 v1(8756,2514) ; v1(9075,2499) 9361,2499 9385.62,2523.62 J7.12@9527.56,2523.62 ; v1(9175,2245) 9455.86,2245 9568.86,2132 10170.37,2132 10393.37,2355 10703,2355 10816,2468 10867.89,2468 10910.89,2511 11059,2511 11109,2461 11109,2458.18 11124.53,2442.65 11505.02,2442.65 11722.02,2659.65 CF1.27@12147.64,2659.65 ; U1.9@9564.65,1305.43 9616.4,1305.43 9618.83,1303 9643.89,1303 9657.89,1317 v1(9661,1317)
  Bottom Layer w8: v1(8756,2514) 8559.51,2514 8227,2846.51 8227,3280.49 8625.86,3679.35 8625.86,3942.77 8847.95,4164.86 9146.23,4164.86 9178.37,4197 9294,4197 9345.05,4248.05 9366.16,4248.05 J5.9@9370.08,4251.97 ; v1@8756,2515 8893.97,2515 8898.97,2520 9051.37,2520 9073.37,2498 9074,2498 v1(9075,2499) 9075.13,2499.13 9138.98,2499.13 9177,2461.12 9177,2246 v1@9176,2245 ; v1(9175,2245) v1@9176,2245 ; v1(9661,1317) 9657.89,1317 9643.89,1303 9581.37,1303 9482,1402.37 9482,1826.37 9175,2133.37 9175,2244 v1@9176,2245
D12: CF1.28 J5.7 J6.10 J7.10 U1.10 | length 8576.5
  Top Layer w8: v1(8611,2487) 8612.8,2487 8629.73,2503.94 J6.10@8681.1,2503.94 ; v1(9126.95,2477) 9127.76,2476.2 9364.2,2476.2 9391.94,2503.94 J7.10@9527.56,2503.94 ; v1(9154.28,2263.83) 9155.9,2265.45 9165.34,2265.45 9166.89,2267 9456.49,2267 9575.49,2148 10163.75,2148 10386.75,2371 10695.02,2371 10808.02,2484 10861.26,2484 10940.26,2563 11066.41,2563 11149.41,2480 11497.12,2480 11726.76,2709.65 CF1.28@12147.64,2709.65 ; U1.10@9564.65,1285.75 9610.64,1285.75 9611.89,1287 9630.11,1287 9637.11,1280 v1(9662,1280)
  Bottom Layer w8: v1(9154.28,2263.83) 9152.7,2262.26 9152.7,2255.7 9141,2244 9141,2144.75 9466,1819.75 9466,1391 9570,1287 9630.11,1287 9637.11,1280 v1(9662,1280) ; v1@9154.82,2263.83 9154.82,2265.96 9161,2272.14 9161,2442.95 v1(9126.95,2477) 9126.89,2477.07 9088.65,2477.07 9088.58,2477 9064.89,2477 9060.89,2473 8782,2473 8769.65,2485.35 8744.21,2485.35 8742.56,2487 8610,2487 8609,2486 8564.88,2486 8211,2839.88 8211,3287.12 8609.14,3685.26 8609.14,3949.69 8841.02,4181.57 9140.32,4181.57 9171.75,4213 9258.28,4213 9291.34,4246.06 J5.7@9291.34,4251.97
D13: CF1.29 J5.5 J6.8 J7.8 U1.11 | length 8536
  Top Layer w8: J6.8@8681.1,2484.25 8728.75,2484.25 v1(8758,2455) ; v1(9074,2451.97) 9363.97,2451.97 9396.25,2484.25 J7.8@9527.56,2484.25 ; v1(9138,2287.56) 9458.56,2287.56 9582.12,2164 10157.12,2164 10380.12,2387 10688.39,2387 10801.39,2500 10854.63,2500 10936.63,2582 11104,2582 11162,2524 11495.86,2524 11731.51,2759.65 CF1.29@12147.64,2759.65 ; U1.11@9564.65,1266.06 9565.18,1265.53 9620.47,1265.53 v1(9621,1265)
  Bottom Layer w8: v1(8758,2455) 8756.5,2456.5 8737.13,2456.5 8731.63,2462 8566.25,2462 8195,2833.25 8195,3293.75 8592.43,3691.17 8592.43,3956.62 8833.81,4198 9133,4198 9186.97,4251.97 J5.5@9212.6,4251.97 ; v1@8758.47,2454.6 8759.58,2453.48 9072.48,2453.48 v1(9074,2451.97) ; v1@9074,2455 9125,2455 9145,2435 9145,2313.56 9140.3,2308.85 9140.3,2293.1 v1@9136.38,2289.18 ; v1(9138,2287.56) 9119,2268.56 9119,2144.12 9450,1813.12 9450,1378.25 9563.25,1265 v1(9621,1265)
